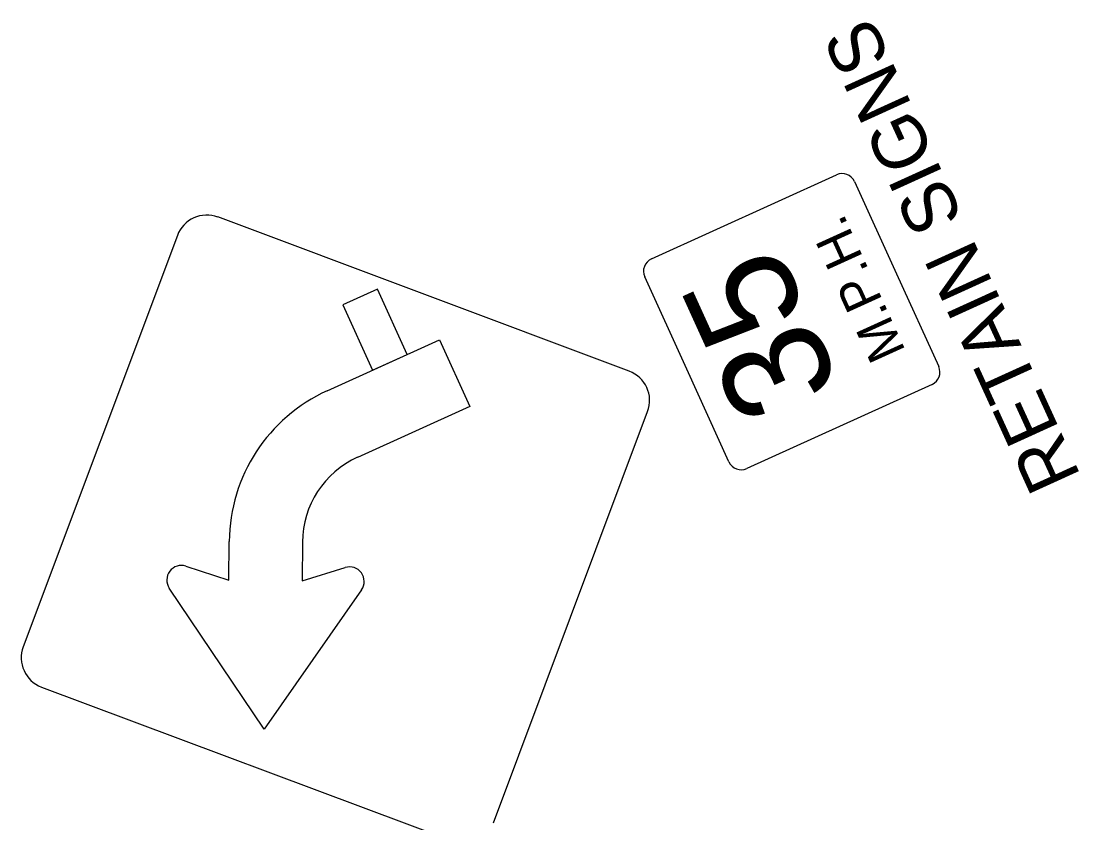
# Model space of a CAD drawing. Extents: x 2096093 to 2099001, y 683546 to 685907.
# Drawn here: x 2096460.7 to 2096598.4, y 683750.8 to 683855.2 of the extents above; entities that cross this region are included whole.
import ezdxf

# ---------------------------------------------------------------- set-up
doc = ezdxf.new("R2010")
doc.units = 0
for name, color, linetype in [('Default', 7, 'Continuous'), ('Exist Sign E Curve Left CELL', 7, 'Continuous'), ('Prop DSN Text', 7, 'Continuous')]:
    doc.layers.add(name, color=color, linetype=linetype)

msp = doc.modelspace()

# ---------------------------------------------------------------- linework, layer by layer
at = {"layer": 'Exist Sign E Curve Left CELL'}
for p, q in [((2096542.74, 683824.24), (2096566.86, 683835.22)), ((2096539.86, 683809.63), (2096486.27, 683829.71)), ((2096481.02, 683827.32), (2096460.94, 683773.73)), ((2096506.43, 683809.76), (2096510.95, 683811.8)), ((2096519.08, 683805.04), (2096504.47, 683798.4)), ((2096519.08, 683805.04), (2096504.47, 683798.4)), ((2096519.08, 683805.04), (2096504.47, 683798.4)), ((2096522.17, 683750.79), (2096542.25, 683804.37)), ((2096463.32, 683768.48), (2096516.91, 683748.4))]:
    msp.add_line(p, q, dxfattribs=at)
for points in [[(2096569.18, 683834.35), (2096574.66, 683822.29)], [(2096547.36, 683809.87), (2096541.87, 683821.93)], [(2096574.66, 683822.29), (2096580.15, 683810.23)], [(2096510.95, 683811.8), (2096507.07, 683820.32), (2096502.56, 683818.27), (2096506.43, 683809.76)], [(2096500.52, 683807.07), (2096515.14, 683813.72), (2096519.08, 683805.04)], [(2096500.52, 683807.07), (2096515.14, 683813.72), (2096519.08, 683805.04)], [(2096500.52, 683807.07), (2096515.14, 683813.72), (2096519.08, 683805.04)], [(2096552.84, 683797.8), (2096547.36, 683809.87)], [(2096579.28, 683807.91), (2096555.16, 683796.94)], [(2096482.13, 683784.22), (2096487.73, 683782.39), (2096487.77, 683787.44)], [(2096482.13, 683784.22), (2096487.73, 683782.39), (2096487.77, 683787.44)], [(2096482.13, 683784.22), (2096487.73, 683782.39), (2096487.77, 683787.44)], [(2096497.29, 683787.36), (2096497.25, 683782.31), (2096502.88, 683784.04)], [(2096497.29, 683787.36), (2096497.25, 683782.31), (2096502.88, 683784.04)], [(2096497.29, 683787.36), (2096497.25, 683782.31), (2096502.88, 683784.04)], [(2096505, 683781.13), (2096492.33, 683762.99), (2096479.96, 683781.34)], [(2096505, 683781.13), (2096492.33, 683762.99), (2096479.96, 683781.34)], [(2096505, 683781.13), (2096492.33, 683762.99), (2096479.96, 683781.34)]]:
    msp.add_lwpolyline(points, dxfattribs=at)
for centre, radius, start, end in [((2096567.58, 683833.62), 1.75, 24.458, 114.458), ((2096484.84, 683825.88), 4.08, 69.458, 159.458), ((2096543.46, 683822.65), 1.75, 114.458, 204.458), ((2096538.43, 683805.8), 4.08, 339.458, 69.458), ((2096578.56, 683809.5), 1.75, 294.458, 24.458), ((2096554.43, 683798.53), 1.75, 204.445, 294.458), ((2096464.76, 683772.3), 4.08, 159.458, 249.458)]:
    msp.add_arc(centre, radius, start, end, dxfattribs=at)
for centre, major_axis, start_param, end_param in [((2096509.54, 683787.26), (-19.82, -9.01), 4.712389, 5.847944), ((2096509.54, 683787.26), (-19.82, -9.01), 4.712389, 5.847944), ((2096509.54, 683787.26), (-19.82, -9.01), 4.712389, 5.847944), ((2096509.54, 683787.26), (-11.15, -5.07), 4.712389, 5.847944), ((2096509.54, 683787.26), (-11.15, -5.07), 4.712389, 5.847944), ((2096509.54, 683787.26), (-11.15, -5.07), 4.712389, 5.847944), ((2096481.54, 683782.41), (-1.73, -0.79), 3.969953, 6.449197), ((2096481.54, 683782.41), (-1.73, -0.79), 3.969953, 6.449197), ((2096481.54, 683782.41), (-1.73, -0.79), 3.969953, 6.449197), ((2096503.44, 683782.23), (1.73, 0.79), 5.246691, 7.725935), ((2096503.44, 683782.23), (1.73, 0.79), 5.246691, 7.725935), ((2096503.44, 683782.23), (1.73, 0.79), 5.246691, 7.725935)]:
    msp.add_ellipse(centre, major_axis=major_axis, ratio=0.999989, start_param=start_param, end_param=end_param, dxfattribs=at)

# ---------------------------------------------------------------- texts
at = {"layer": 'Default'}
msp.add_text('RETAIN SIGNS', height=7, rotation=114.4888, dxfattribs=at).set_placement((2096598.72, 683795.9))
at = {"layer": 'Prop DSN Text'}
for s, height, p in [('M.P.H.', 4.86, (2096575.89, 683812.24)), ('35', 14, (2096567.53, 683807.62))]:
    msp.add_text(s, height=height, rotation=114.458, dxfattribs=at).set_placement(p)

doc.saveas('drawing.dxf')
